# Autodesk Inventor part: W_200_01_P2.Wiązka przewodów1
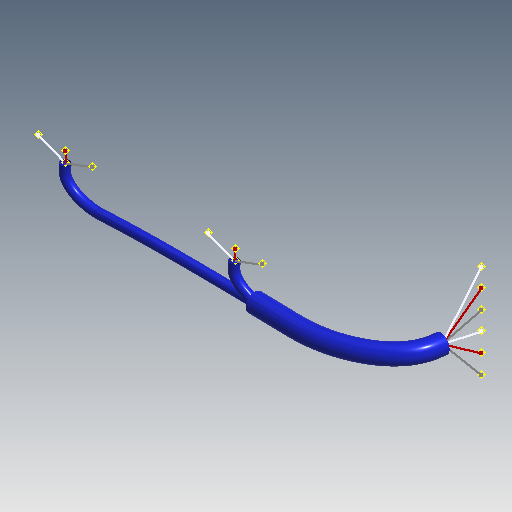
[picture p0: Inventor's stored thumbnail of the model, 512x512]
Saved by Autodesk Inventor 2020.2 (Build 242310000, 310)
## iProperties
Manager: www.cadconsulting.pl
Company: Fabian Stasiak CAD Consulting
Created: 2014-09
Part Number: W_200_01_P2.Wiązka przewodów1
Material: Ogólne
Document SubType Name: Modelowanie
Designer: F.Stasiak
Appearance: Ogólne
Catalog Web Link: www.expertbooks.pl
Key:2|1|1|0|4|0|0|0|2|0|0|0|Level:2: <CableProperty entityType="Connector" version="1.0"><ID editable="" value=""/><UserDefined/><Name editable="True" value=""/><Refdes editable="True" value="S_150
Key:2|1|1|0|4|0|0|0|3|0|0|0|Level:2: <CableProperty entityType="Connector" version="1.0"><ID editable="" value=""/><UserDefined/><Name editable="True" value=""/><Refdes editable="True" value="S_150
Key:2|1|1|0|4|0|0|0|8|0|0|0|Level:2: <CableProperty entityType="Connector" version="1.0"><ID editable="" value=""/><UserDefined/><Name editable="True" value=""/><Refdes editable="True" value="LISTW
GlobalPropertyList: <PropertyList/>
Author: F.Stasiak
Subject: Zbiór ćwiczeń. Autodesk Inventor 2020. Kurs Professional
## Parameters: d2 = 0, d3 = 0, d4 = 0, d5 = 0, d6 = 0, d7 = 0
